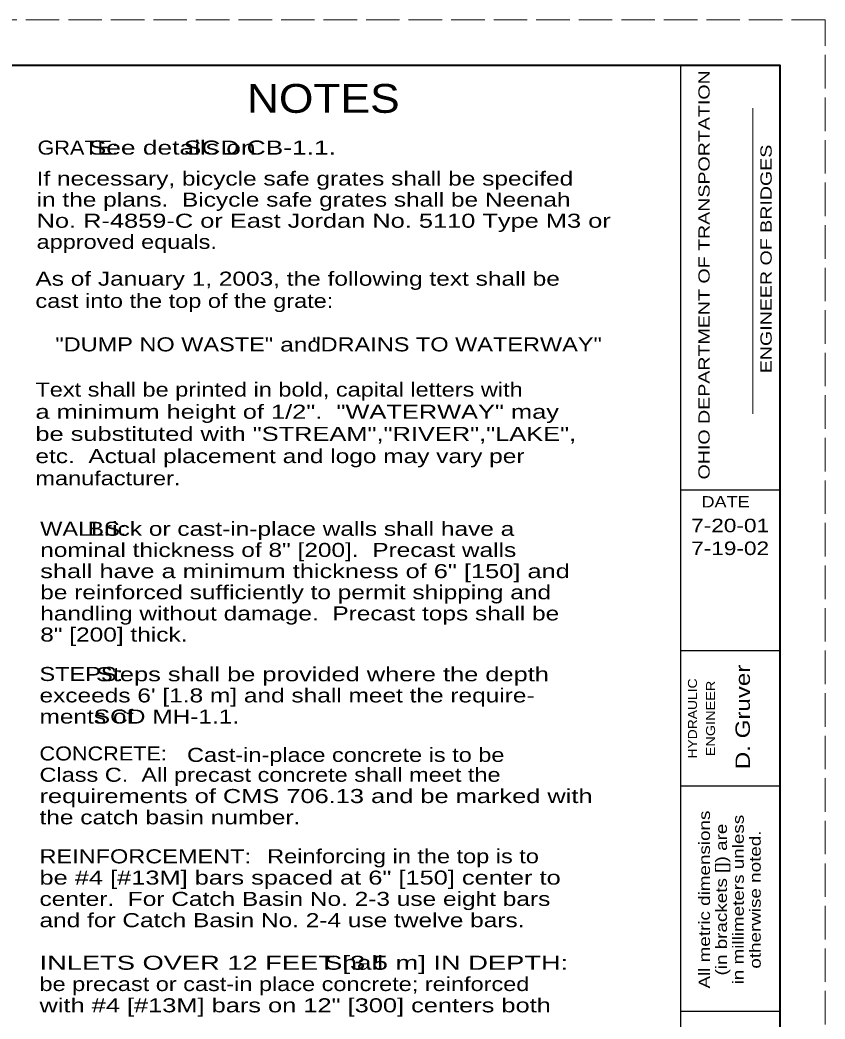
# Model space of a CAD drawing. Extents: x 1083.1 to 1117.1, y 697.4 to 719.4.
# Drawn here: x 1108.19 to 1117.13, y 708.27 to 719.35 of the extents above; entities that cross this region are included whole.
import ezdxf
from ezdxf.enums import TextEntityAlignment as Align

# ---------------------------------------------------------------- set-up
doc = ezdxf.new("R2010")
doc.units = 0
doc.header["$LTSCALE"] = 0.062
doc.linetypes.add('LONG_DASHED', pattern=[7.5, 6, -1.5])
doc.layers.add('1', color=7, linetype='Continuous', lineweight=13)

msp = doc.modelspace()

# ---------------------------------------------------------------- linework, layer by layer
at = {"layer": '1', "lineweight": 25}
for p, q in [((1085.12642, 718.85408), (1116.62642, 718.85408)), ((1115.52642, 697.85408), (1115.52642, 718.85408)), ((1116.62642, 718.85408), (1116.62642, 697.85408)), ((1116.62642, 714.13825), (1115.52642, 714.13825)), ((1116.62642, 712.35408), (1115.52642, 712.35408)), ((1116.62642, 710.85408), (1115.52642, 710.85408)), ((1116.62642, 708.35408), (1115.52642, 708.35408))]:
    msp.add_line(p, q, dxfattribs=at)
at = {"layer": '1'}
msp.add_line((1116.32517, 714.98508), (1116.32517, 718.37517), dxfattribs=at)
at = {"layer": '1', "linetype": 'LONG_DASHED'}
msp.add_lwpolyline([(1083.12642, 697.35408), (1117.12642, 697.35408), (1117.12642, 719.35408), (1083.12642, 719.35408)], close=True, dxfattribs=at)
at = {"layer": '1', "lineweight": 40}
msp.add_lwpolyline([(1085.12642, 718.85408), (1116.62642, 718.85408), (1116.62642, 697.85408), (1085.12642, 697.85408)], close=True, dxfattribs=at)
msp.add_lwpolyline([(1085.12642, 718.85408), (1116.62642, 718.85408), (1116.62642, 697.85408), (1085.12642, 697.85408)], close=True, dxfattribs=at)

# ---------------------------------------------------------------- texts
at = {"layer": '1'}
for s, height, width, p in [('OHIO DEPARTMENT OF TRANSPORTATION', 0.125, 1.3, (1115.84633, 716.52633)), ('ENGINEER OF BRIDGES', 0.125, 1.3, (1116.53467, 716.70312)), ('D. Gruver', 0.16, 1.25, (1116.29325, 711.62233)), ('HYDRAULIC', 0.1, 1.15, (1115.7055, 711.60517)), ('ENGINEER', 0.1, 1.2, (1115.90642, 711.60521)), ('All metric dimensions', 0.125, 1.25, (1115.85025, 709.59617)), ('(in brackets []) are', 0.125, 1.25, (1116.03775, 709.59617)), ('in millimeters unless', 0.125, 1.25, (1116.22525, 709.59621)), ('otherwise noted.', 0.125, 1.25, (1116.41275, 709.59617))]:
    msp.add_text(s, height=height, rotation=90, dxfattribs=dict(at, width=width)).set_placement(p, align=Align.CENTER)
for s, height, width, p in [('NOTES', 0.32, 1.15, (1110.71158, 718.32417)), ('GRATE:', 0.156, 1.15, (1108.38875, 717.86033)), ('       See details on            ', 0.156, 1.4, (1108.38875, 717.86033)), ('                    SCD CB-1.1. ', 0.156, 1.4, (1108.38875, 717.86033)), ('If necessary, bicycle safe grates shall be specifed ', 0.156, 1.3, (1108.37817, 717.51708)), ('in the plans.  Bicycle safe grates shall be Neenah ', 0.156, 1.3, (1108.37817, 717.28308)), ('No. R-4859-C or East Jordan No. 5110 Type M3 or', 0.156, 1.35, (1108.37817, 717.04908)), ('approved equals.', 0.156, 1.25, (1108.37817, 716.81508)), ('As of January 1, 2003, the following text shall be ', 0.156, 1.3, (1108.36533, 716.40617)), ('cast into the top of the grate: ', 0.156, 1.25, (1108.36533, 716.16017)), ('   "DUMP NO WASTE"      "DRAINS TO WATERWAY"', 0.156, 1.25, (1108.36917, 715.67767)), (' and', 0.156, 1.3, (1111.006, 715.67508)), ('Text shall be printed in bold, capital letters with ', 0.156, 1.25, (1108.36533, 715.17617)), ('a minimum height of 1/2".  "WATERWAY" may ', 0.156, 1.35, (1108.36533, 714.93017)), ('be substituted with "STREAM","RIVER","LAKE", ', 0.156, 1.35, (1108.36533, 714.68417)), ('etc.  Actual placement and logo may vary per ', 0.156, 1.3, (1108.36533, 714.43817)), ('manufacturer.', 0.156, 1.25, (1108.36533, 714.19217)), ('WALLS: ', 0.156, 1.25, (1108.41842, 713.63183)), ('       Brick or cast-in-place walls shall have a', 0.156, 1.3, (1108.41842, 713.63142)), ('nominal thickness of 8" [200].  Precast walls', 0.156, 1.3, (1108.41842, 713.39675)), ('shall have a minimum thickness of 6" [150] and', 0.156, 1.35, (1108.41842, 713.16208)), ('be reinforced sufficiently to permit shipping and', 0.156, 1.3, (1108.41842, 712.92742)), ('handling without damage.  Precast tops shall be', 0.156, 1.3, (1108.41842, 712.69275)), ('8" [200] thick.', 0.156, 1.3, (1108.41842, 712.45808)), ('STEPS:', 0.156, 1.25, (1108.41058, 712.02075)), ('        Steps shall be provided where the depth', 0.156, 1.35, (1108.41058, 712.01792)), ("exceeds 6' [1.8 m] and shall meet the require-", 0.156, 1.3, (1108.41058, 711.78325)), ('ments of', 0.156, 1.3, (1108.41058, 711.54858)), ('        SCD MH-1.1.', 0.156, 1.3, (1108.41058, 711.54858)), ('CONCRETE:', 0.156, 1.15, (1108.41058, 711.139)), ('Cast-in-place concrete is to be', 0.156, 1.25, (1110.04742, 711.12317)), ('Class C.  All precast concrete shall meet the', 0.156, 1.25, (1108.41058, 710.90292)), ('requirements of CMS 706.13 and be marked with', 0.156, 1.35, (1108.41058, 710.66675)), ('the catch basin number.', 0.156, 1.3, (1108.41058, 710.43067)), ('REINFORCEMENT:', 0.156, 1.25, (1108.41058, 709.99792)), ('Reinforcing in the top is to', 0.156, 1.25, (1110.93667, 709.999)), ('be #4 [#13M] bars spaced at 6" [150] center to', 0.156, 1.35, (1108.41058, 709.76183)), ('center.  For Catch Basin No. 2-3 use eight bars', 0.156, 1.3, (1108.41058, 709.52567)), ('and for Catch Basin No. 2-4 use twelve bars.', 0.156, 1.3, (1108.41058, 709.28958)), ('INLETS OVER 12 FEET [3.5 m] IN DEPTH:', 0.156, 1.45, (1108.41058, 708.81742)), ('                                       Shall ', 0.156, 1.4, (1108.41058, 708.81742)), ('be precast or cast-in place concrete; reinforced', 0.156, 1.25, (1108.41058, 708.58133)), ('with #4 [#13M] bars on 12" [300] centers both', 0.156, 1.35, (1108.41058, 708.34517))]:
    msp.add_text(s, height=height, dxfattribs=dict(at, width=width)).set_placement(p)
for s, height, width, p in [('DATE', 0.125, 1.2, (1116.02312, 713.94683)), ('7-20-01', 0.15, 1.25, (1116.07346, 713.67133)), ('7-19-02', 0.15, 1.25, (1116.07346, 713.41825))]:
    msp.add_text(s, height=height, dxfattribs=dict(at, width=width)).set_placement(p, align=Align.CENTER)

doc.saveas('drawing.dxf')
